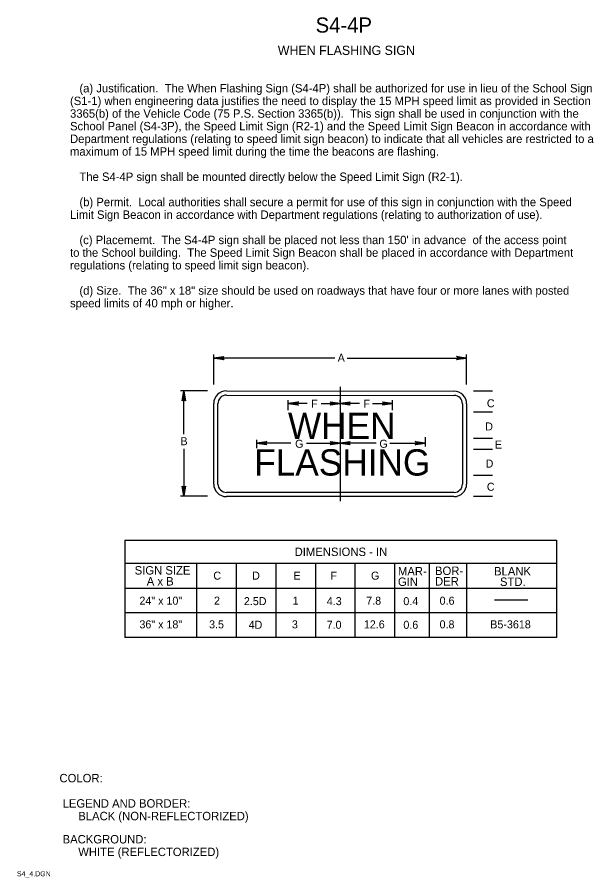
# Model space of a CAD drawing. Extents: x 0.013 to 0.184, y 0.004 to 0.259.
import ezdxf

# ---------------------------------------------------------------- set-up
doc = ezdxf.new("R2010")
doc.units = 0
for name, color, linetype in [('1', 7, 'Continuous'), ('2', 7, 'Continuous'), ('3', 7, 'Continuous')]:
    doc.layers.add(name, color=color, linetype=linetype)

# ---------------------------------------------------------------- blocks, each defined once
blk = doc.blocks.new('RARROW')
at = {"layer": '3'}
for p, q in [((-2.156, 0.285), (-2.2665, 0.384625)), ((-2.2665, 0.384625), (0, 0)), ((0, 0), (-2.2665, -0.379125)), ((-2.156, 0.285), (-2.075625, 0.12075)), ((0, 0), (-2.156, 0.285)), ((-2.14975, -0.2705), (0, 0)), ((-2.075625, 0.12075), (0, 0)), ((0, 0), (-2.074, -0.108)), ((-2.2665, -0.379125), (-2.14975, -0.2705)), ((-2.074, -0.108), (-2.14975, -0.2705))]:
    blk.add_line(p, q, dxfattribs=at)

msp = doc.modelspace()

# ---------------------------------------------------------------- linework, layer by layer
at = {"layer": '1'}
msp.add_line((0.1085, 0.14961), (0.1085, 0.11561), dxfattribs=at)
at = {"layer": '3'}
for p, q in [((0.071, 0.15024), (0.071, 0.15911)), ((0.146, 0.15024), (0.146, 0.15911)), ((0.10695, 0.15811), (0.071, 0.15811)), ((0.11052, 0.15811), (0.146, 0.15811)), ((0.0691, 0.14836), (0.06112, 0.14836)), ((0.06212, 0.13554), (0.06212, 0.14836)), ((0.07475, 0.14836), (0.14225, 0.14824)), ((0.148, 0.14836), (0.15363, 0.14836)), ((0.07475, 0.14711), (0.14225, 0.14699)), ((0.09312, 0.14261), (0.09312, 0.14561)), ((0.1085, 0.14511), (0.1085, 0.14561)), ((0.124, 0.14261), (0.124, 0.14561)), ((0.071, 0.12074), (0.071, 0.14461)), ((0.07225, 0.12074), (0.07225, 0.14461)), ((0.09875, 0.14461), (0.09312, 0.14461)), ((0.10288, 0.14461), (0.1085, 0.14461)), ((0.11425, 0.14461), (0.1085, 0.14461)), ((0.11813, 0.14461), (0.124, 0.14461)), ((0.14475, 0.14449), (0.14475, 0.12074)), ((0.146, 0.14449), (0.146, 0.12074)), ((0.148, 0.14211), (0.15363, 0.14211)), ((0.08375, 0.13136), (0.08375, 0.13386)), ((0.09388, 0.13286), (0.08375, 0.13286)), ((0.0985, 0.13286), (0.1085, 0.13286)), ((0.11913, 0.13286), (0.1085, 0.13286)), ((0.12325, 0.13286), (0.13375, 0.13286)), ((0.13375, 0.13461), (0.13375, 0.13186)), ((0.148, 0.13436), (0.15363, 0.13436)), ((0.06212, 0.13122), (0.06212, 0.11711)), ((0.148, 0.13111), (0.15363, 0.13111)), ((0.148, 0.12336), (0.15363, 0.12336)), ((0.14225, 0.11824), (0.07475, 0.11824)), ((0.0691, 0.11711), (0.06112, 0.11711)), ((0.14225, 0.11699), (0.07475, 0.11699)), ((0.148, 0.11711), (0.15363, 0.11711)), ((0.04462, 0.10412), (0.17263, 0.10412)), ((0.04462, 0.10412), (0.04462, 0.07525)), ((0.17263, 0.10412), (0.17263, 0.07525)), ((0.17263, 0.09713), (0.04462, 0.09713)), ((0.06588, 0.09713), (0.06588, 0.07525)), ((0.07762, 0.09713), (0.07762, 0.07525)), ((0.08937, 0.09713), (0.08937, 0.07525)), ((0.10113, 0.09713), (0.10113, 0.07525)), ((0.11288, 0.09713), (0.11288, 0.07525)), ((0.12462, 0.09713), (0.12462, 0.07525)), ((0.12462, 0.09713), (0.12462, 0.07525)), ((0.13487, 0.09713), (0.13487, 0.07525)), ((0.146, 0.097), (0.146, 0.07525)), ((0.17263, 0.08975), (0.04462, 0.08975)), ((0.15424, 0.08638), (0.16411, 0.08638)), ((0.17263, 0.0825), (0.04462, 0.0825)), ((0.17263, 0.07525), (0.04462, 0.07525))]:
    msp.add_line(p, q, dxfattribs=at)
for centre, radius, start, end in [((0.07475, 0.14461), 0.00375, 90, 180), ((0.14226, 0.14451), 0.00374, 359.7012, 89.7012), ((0.07478, 0.14458), 0.00253, 90.5918, 180.5918), ((0.14226, 0.14451), 0.00249, 359.5514, 89.5514), ((0.07475, 0.12074), 0.00375, 180, 270), ((0.07475, 0.12074), 0.0025, 180, 270), ((0.14227, 0.12073), 0.00373, 270.1007, 0.1007), ((0.14227, 0.12073), 0.00248, 270.1515, 0.1515)]:
    msp.add_arc(centre, radius, start, end, dxfattribs=at)

# ---------------------------------------------------------------- block references
at = {"layer": '3', "xscale": 0.0013236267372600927, "yscale": 0.001309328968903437}
for p, rotation in [((0.071, 0.15811), 180), ((0.06212, 0.14836), 90), ((0.09312, 0.14461), 180), ((0.1085, 0.14461), 180), ((0.08375, 0.13286), 180), ((0.1085, 0.13286), 180), ((0.06212, 0.11711), -90)]:
    msp.add_blockref('RARROW', p, dxfattribs=dict(at, rotation=rotation))
for p in [(0.146, 0.15811), (0.1085, 0.14461), (0.124, 0.14461), (0.1085, 0.13286), (0.13375, 0.13286)]:
    msp.add_blockref('RARROW', p, dxfattribs=at)

# ---------------------------------------------------------------- texts
at = {"layer": '1'}
for s, height, p in [('S4-4P', 0.0045, (0.10121, 0.25462)), ('WHEN FLASHING SIGN', 0.0027503, (0.09, 0.248)), ('COLOR:', 0.0025, (0.02525, 0.03225)), (' LEGEND AND BORDER:', 0.0024998, (0.02525, 0.02475)), ('      BLACK (NON-REFLECTORIZED)', 0.0024998, (0.02525, 0.021)), (' BACKGROUND:', 0.0024998, (0.02525, 0.01413)), ('      WHITE (REFLECTORIZED)', 0.0024998, (0.02525, 0.01038)), ('S4_4.DGN', 0.0015, (0.01263, 0.00438))]:
    msp.add_text(s, height=height, dxfattribs=at).set_placement(p)
at = {"layer": '2'}
for s, height, p in [('   (a) Justification.  The When Flashing Sign (S4-4P) shall be authorized for use in lieu of the School Sign', 0.00249975, (0.02838, 0.23688)), ('(S1-1) when engineering data justifies the need to display the 15 MPH speed limit as provided in Section', 0.00249975, (0.02838, 0.23313)), ('3365(b) of the Vehicle Code (75 P.S. Section 3365(b)).  This sign shall be used in conjunction with the', 0.00249975, (0.02838, 0.22938)), ('School Panel (S4-3P), the Speed Limit Sign (R2-1) and the Speed Limit Sign Beacon in accordance with', 0.0024998, (0.02838, 0.22563)), ('Department regulations (relating to speed limit sign beacon) to indicate that all vehicles are restricted to a ', 0.00249975, (0.02838, 0.22188)), ('maximum of 15 MPH speed limit during the time the beacons are flashing. ', 0.0024998, (0.02838, 0.21813)), ('   The S4-4P sign shall be mounted directly below the Speed Limit Sign (R2-1).', 0.0024998, (0.02838, 0.21063)), ('   (b) Permit.  Local authorities shall secure a permit for use of this sign in conjunction with the Speed', 0.00249975, (0.02838, 0.20313)), ('Limit Sign Beacon in accordance with Department regulations (relating to authorization of use).', 0.0024998, (0.02838, 0.19938)), ("   (c) Placememt.  The S4-4P sign shall be placed not less than 150' in advance  of the access point ", 0.00249975, (0.02838, 0.19188)), ('to the School building.  The Speed Limit Sign Beacon shall be placed in accordance with Department', 0.0024998, (0.02838, 0.18813)), ('regulations (relating to speed limit sign beacon).', 0.0024998, (0.02838, 0.18438)), ('   (d) Size.  The 36" x 18" size should be used on roadways that have four or more lanes with posted', 0.0024998, (0.02838, 0.17688)), ('speed limits of 40 mph or higher.', 0.0024998, (0.02838, 0.17313))]:
    msp.add_text(s, height=height, dxfattribs=at).set_placement(p)
at = {"layer": '3'}
for s, height, p in [('A', 0.00238, (0.10775, 0.15699)), ('F', 0.00238, (0.09988, 0.14336)), ('F', 0.00238, (0.11538, 0.14336)), ('C', 0.00238, (0.152, 0.14349)), ('WHEN', 0.007812, (0.093, 0.13411)), ('D', 0.00238, (0.1515, 0.13661)), ('B', 0.00238, (0.06112, 0.13224)), ('G', 0.00238, (0.09513, 0.13149)), ('G', 0.00238, (0.12012, 0.13149)), ('E', 0.00238, (0.15438, 0.13124)), ('FLASHING', 0.007812, (0.083, 0.12324)), ('D', 0.00238, (0.15163, 0.12561)), ('C', 0.00238, (0.152, 0.11874)), ('DIMENSIONS - IN', 0.0024998, (0.09499, 0.09938)), ('SIGN SIZE', 0.0025, (0.04754, 0.09388)), ('C', 0.00238, (0.07088, 0.09237)), ('D', 0.00238, (0.08238, 0.09237)), ('E', 0.00238, (0.09463, 0.09237)), ('F', 0.00238, (0.10562, 0.09237)), ('G', 0.00238, (0.11763, 0.09237)), ('MAR-', 0.0025, (0.12563, 0.09362)), ('BOR-', 0.0025, (0.13662, 0.09375)), ('BLANK', 0.0025, (0.15413, 0.09362)), ('A x B', 0.0025, (0.05113, 0.09063)), ('GIN', 0.0025, (0.12563, 0.0905)), ('DER', 0.0025, (0.13662, 0.09062)), ('STD.', 0.0025, (0.15588, 0.0905)), ('24" x 10"', 0.002375, (0.04896, 0.08494)), ('2', 0.00238, (0.07107, 0.08494)), ('2.5D', 0.002375, (0.07994, 0.08481)), ('1', 0.00238, (0.09439, 0.08494)), ('4.3', 0.002375, (0.10453, 0.08481)), ('7.8', 0.002375, (0.11623, 0.08494)), ('0.4', 0.002375, (0.12723, 0.08481)), ('0.6', 0.002375, (0.13799, 0.08494)), ('36" x 18"', 0.002375, (0.04896, 0.07792)), ('3.5', 0.002375, (0.06962, 0.07792)), ('4D', 0.002375, (0.08135, 0.0778)), ('3', 0.00238, (0.09418, 0.07792)), ('7.0', 0.002375, (0.10449, 0.0778)), ('12.6', 0.002375, (0.11552, 0.07792)), ('0.6', 0.002375, (0.12724, 0.0778)), ('0.8', 0.002375, (0.13798, 0.07792)), ('B5-3618', 0.002375, (0.15301, 0.07792))]:
    msp.add_text(s, height=height, dxfattribs=at).set_placement(p)

doc.saveas('drawing.dxf')
